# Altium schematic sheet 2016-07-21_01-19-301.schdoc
size 247 x 165 mm; SheetNumber: 1; SheetTotal: 1
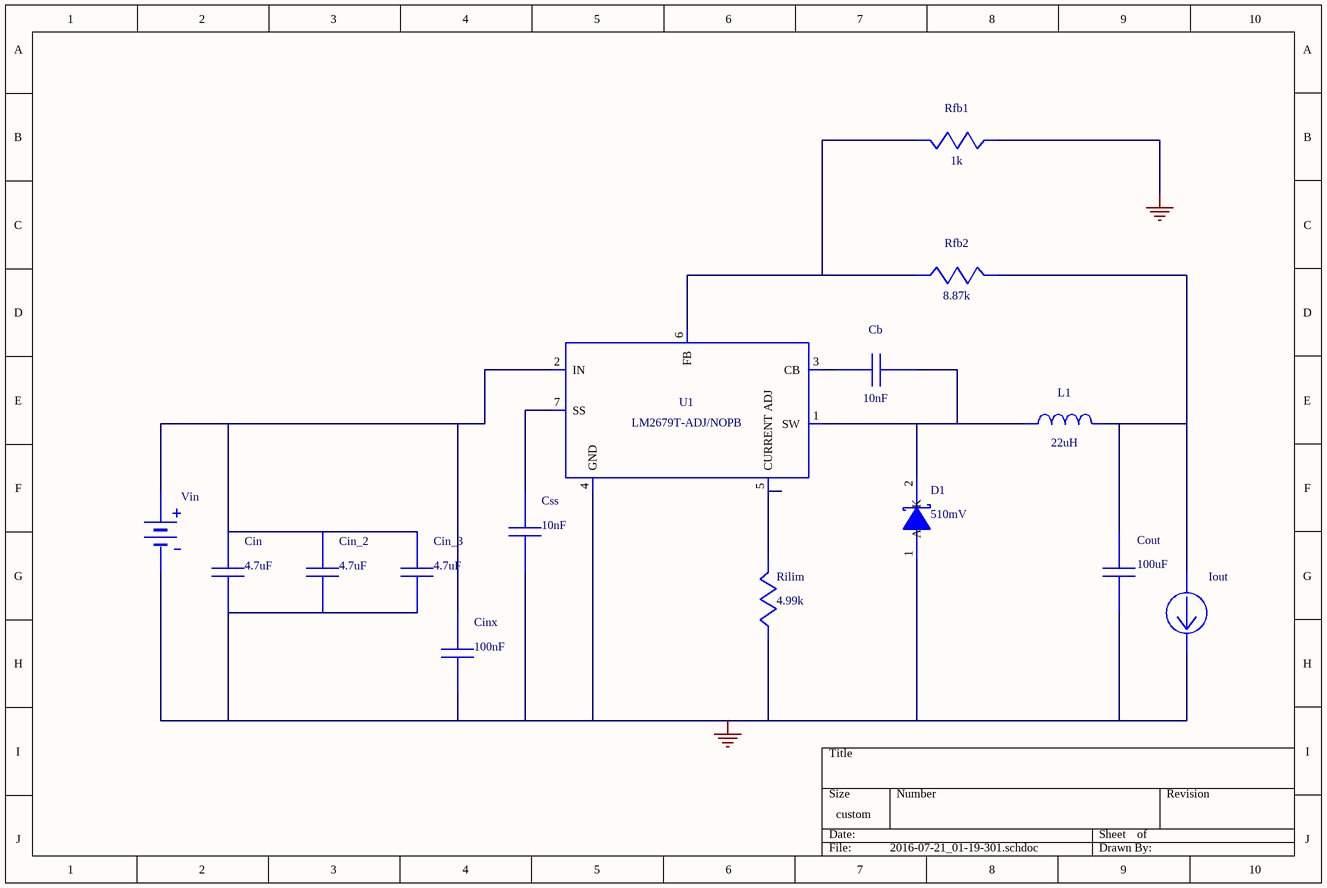
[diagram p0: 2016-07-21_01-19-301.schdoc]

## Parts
Cb  value 10nF  (hidden comment: GRM216R71H103KA01D)
Cin  value 4.7uF  (hidden comment: GRM31CR71H475KA12L)
Cin_2  value 4.7uF  (hidden comment: GRM31CR71H475KA12L)
Cin_3  value 4.7uF  (hidden comment: GRM31CR71H475KA12L)
Cinx  value 100nF  (hidden comment: C0805C104K5RACTU)
Cout  value 100uF  (hidden comment: GENERIC_CAPACITOR)
Css  value 10nF  (hidden comment: GRM216R71H103KA01D)
D1  value 510mV  (hidden comment: 50WQ04FNPBF)
Iout  WB_CURRENT_LOAD  (value not drawn)
L1  value 22uH  (hidden comment: PM2110-220K-RC)
Rfb1  value 1k  (hidden comment: CRCW06031K00FKEA)
Rfb2  value 8.87k  (hidden comment: CRCW06038K87FKEA)
Rilim  value 4.99k  (hidden comment: CRCW06034K99FKEA)
U1  LM2679T-ADJ/NOPB
Vin  WB_BATTERY  (value not drawn)

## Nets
0: Cin.2 Cin_2.2 Cin_3.2 Cinx.2 Cout.2 Css.2 D1.1(A) D1.3(A) Iout.2(-) Rfb1.2 Rilim.2 U1.4(GND) Vin.2(-)
NetCb_1: Cb.1 D1.2(K) L1.1 U1.1(SW)
NetCb_2: Cb.2 U1.3(CB)
NetCin_1: Cin.1 Cin_2.1 Cin_3.1 Cinx.1 U1.2(IN) Vin.1(+)
NetCout_1: Cout.1 Iout.1(+) L1.2 Rfb2.1
NetCss_1: Css.1 U1.7(SS)
NetRfb1_1: Rfb1.1 Rfb2.2 U1.6(FB)
NetRilim_1: Rilim.1 U1.5(CURRENT_ADJ)

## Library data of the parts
Cb Css = GRM216R71H103KA01D: GRM216R71H103KA0; Manufacturer Name: MuRata
Cin Cin_2 Cin_3 = GRM31CR71H475KA12L: GRM31CR71H475KA1; Manufacturer Name: MuRata
Cinx = C0805C104K5RACTU: Manufacturer Name: Kemet
Cout = GENERIC_CAPACITOR: 16SVPC100M; Manufacturer Name: Panasonic
D1 = 50WQ04FNPBF: Manufacturer Name: Vishay-Semiconductor
L1 = PM2110-220K-RC: Manufacturer Name: Bourns
Rfb1 = CRCW06031K00FKEA: Manufacturer Name: Vishay-Dale
Rfb2 = CRCW06038K87FKEA: Manufacturer Name: Vishay-Dale
Rilim = CRCW06034K99FKEA: Manufacturer Name: Vishay-Dale
U1 = LM2679T-ADJ/NOPB: Manufacturer Name: Texas Instruments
